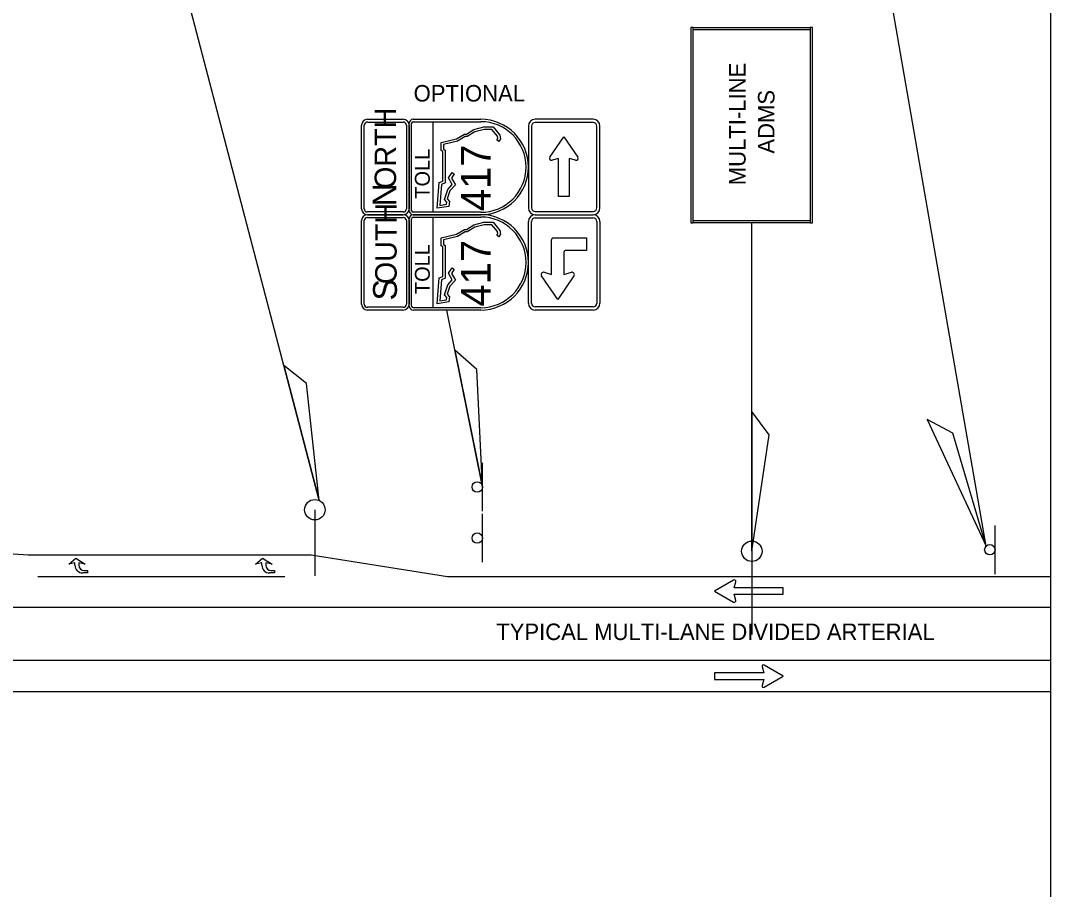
# Model space of a CAD drawing. Extents: x -830008.4 to -829992.7, y 1290284.1 to 1290294.4.
# Drawn here: x -829997.148 to -829992.774, y 1290288.685 to 1290292.375 of the extents above; entities that cross this region are included whole.
import ezdxf

# ---------------------------------------------------------------- set-up
doc = ezdxf.new("R2010")
doc.units = 0
for name, color, linetype in [('1', 7, 'Continuous'), ('DirArrowsPavt', 7, 'Continuous'), ('LaneDirArrow', 7, 'Continuous'), ('OOCEA Logo', 7, 'Continuous'), ('PlotBorder_dp', 7, 'Continuous'), ('SheetBorder_dp', 7, 'Continuous'), ('SheetLines_dp', 7, 'Continuous'), ('SignPanel', 7, 'Continuous')]:
    doc.layers.add(name, color=color, linetype=linetype)

msp = doc.modelspace()

# ---------------------------------------------------------------- linework, layer by layer
at = {"layer": '1'}
for p, q in [((-829993.0471, 1290290.1429), (-829993.4953, 1290292.7228)), ((-829995.8801, 1290290.3367), (-829996.4857, 1290292.6472)), ((-829994.0424, 1290290.1209), (-829994.0424, 1290291.516)), ((-829995.1866, 1290290.3939), (-829995.3374, 1290291.1454)), ((-829997.0749, 1290290.1056), (-829995.9149, 1290290.1056)), ((-829995.9149, 1290290.1056), (-829995.3349, 1290290.0133)), ((-829997.0749, 1290290.0133), (-829996.0258, 1290290.0133)), ((-829995.3349, 1290290.0133), (-829992.7742, 1290290.0133)), ((-829998.578, 1290289.8838), (-829993.659, 1290289.8838)), ((-829993.659, 1290289.8838), (-829992.7742, 1290289.8838)), ((-829998.4483, 1290289.6579), (-829992.7742, 1290289.6579)), ((-829997.6499, 1290289.5251), (-829992.7742, 1290289.5251))]:
    msp.add_line(p, q, dxfattribs=at)
msp.add_arc((-829997.0749, 1290291.317), 1.2114, 238.3217, 270, dxfattribs=at)
at = {"layer": 'DirArrowsPavt'}
for p, q in [((-829996.8778, 1290290.0388), (-829996.8642, 1290290.0388)), ((-829996.0841, 1290290.0388), (-829996.0704, 1290290.0388))]:
    msp.add_line(p, q, dxfattribs=at)
for points in [[(-829996.9175, 1290290.0616), (-829996.9175, 1290290.0721), (-829996.9442, 1290290.0655), (-829996.9142, 1290290.0921), (-829996.8742, 1290290.0655), (-829996.9008, 1290290.0721), (-829996.9008, 1290290.0618)], [(-829996.1237, 1290290.0616), (-829996.1237, 1290290.0721), (-829996.1504, 1290290.0655), (-829996.1204, 1290290.0921), (-829996.0804, 1290290.0655), (-829996.1071, 1290290.0721), (-829996.1071, 1290290.0618)], [(-829996.8642, 1290290.0388), (-829996.8642, 1290290.0288), (-829996.8847, 1290290.0288)], [(-829996.0704, 1290290.0388), (-829996.0704, 1290290.0288), (-829996.0909, 1290290.0288)]]:
    msp.add_lwpolyline(points, dxfattribs=at)
for centre, radius in [((-829996.8847, 1290290.0616), 0.0328), ((-829996.8778, 1290290.0618), 0.023), ((-829996.0909, 1290290.0616), 0.0328), ((-829996.0841, 1290290.0618), 0.023)]:
    msp.add_arc(centre, radius, 180, 270, dxfattribs=at)
at = {"layer": 'LaneDirArrow'}
for p, q in [((-829994.1196, 1290289.9986), (-829994.2004, 1290289.952)), ((-829994.1173, 1290289.9659), (-829994.1105, 1290289.9916)), ((-829993.9087, 1290289.9659), (-829994.1173, 1290289.9659)), ((-829993.9087, 1290289.9381), (-829993.9087, 1290289.9659)), ((-829994.2004, 1290289.952), (-829994.1196, 1290289.9054)), ((-829994.1173, 1290289.9381), (-829993.9087, 1290289.9381)), ((-829994.1105, 1290289.9124), (-829994.1173, 1290289.9381)), ((-829993.9986, 1290289.6301), (-829993.9917, 1290289.6044)), ((-829993.9087, 1290289.5905), (-829993.9895, 1290289.6372)), ((-829993.9917, 1290289.6044), (-829994.2004, 1290289.6044)), ((-829994.2004, 1290289.6044), (-829994.2004, 1290289.5767)), ((-829994.2004, 1290289.5767), (-829993.9917, 1290289.5767)), ((-829993.9917, 1290289.5767), (-829993.9986, 1290289.551)), ((-829993.9895, 1290289.5439), (-829993.9087, 1290289.5905))]:
    msp.add_line(p, q, dxfattribs=at)
for centre, start, end in [((-829994.1165, 1290289.9932), 345, 120), ((-829994.1165, 1290289.9108), 240, 15), ((-829993.9926, 1290289.6318), 60, 195), ((-829993.9926, 1290289.5493), 165, 300)]:
    msp.add_arc(centre, 0.00625, start, end, dxfattribs=at)
at = {"layer": 'OOCEA Logo'}
for p, q in [((-829995.8985, 1290290.2973), (-829995.8985, 1290290.0166)), ((-829994.0424, 1290290.1209), (-829994.0424, 1290289.7674))]:
    msp.add_line(p, q, dxfattribs=at)
for centre in [(-829995.8985, 1290290.2973), (-829995.8985, 1290290.2973), (-829994.0424, 1290290.1209)]:
    msp.add_circle(centre, 0.0434, dxfattribs=at)
at = {"layer": 'PlotBorder_dp'}
for p, q in [((-829995.1866, 1290290.291), (-829995.1866, 1290290.4968)), ((-829995.1866, 1290290.074), (-829995.1866, 1290290.2798)), ((-829993.0094, 1290290.0244), (-829993.0094, 1290290.2302))]:
    msp.add_line(p, q, dxfattribs=at)
for centre in [(-829995.2087, 1290290.3939), (-829995.2087, 1290290.1769), (-829993.0315, 1290290.1273)]:
    msp.add_circle(centre, 0.0221, dxfattribs=at)
at = {"layer": 'SheetBorder_dp'}
for p, q in [((-829995.2966, 1290291.8721), (-829995.2632, 1290291.8929)), ((-829995.2602, 1290291.8823), (-829995.2925, 1290291.8622)), ((-829995.2632, 1290291.8929), (-829995.2548, 1290291.8929)), ((-829995.2518, 1290291.8823), (-829995.2602, 1290291.8823)), ((-829995.2548, 1290291.8929), (-829995.2238, 1290291.9117)), ((-829995.2196, 1290291.9019), (-829995.2518, 1290291.8823)), ((-829995.2238, 1290291.9117), (-829995.1814, 1290291.9233)), ((-829995.18, 1290291.9127), (-829995.2196, 1290291.9019)), ((-829995.1814, 1290291.9233), (-829995.1418, 1290291.9233)), ((-829995.1468, 1290291.9127), (-829995.18, 1290291.9127)), ((-829995.1232, 1290291.8839), (-829995.1468, 1290291.9127)), ((-829995.1418, 1290291.9233), (-829995.1135, 1290291.8887)), ((-829995.1209, 1290291.8745), (-829995.1232, 1290291.8839)), ((-829995.1135, 1290291.8887), (-829995.1095, 1290291.8723)), ((-829994.9003, 1290291.7947), (-829994.8411, 1290291.8809)), ((-829994.8411, 1290291.8809), (-829994.7819, 1290291.7947)), ((-829995.3624, 1290291.8568), (-829995.2966, 1290291.8721)), ((-829995.3624, 1290291.823), (-829995.3624, 1290291.8568)), ((-829995.2925, 1290291.8622), (-829995.3518, 1290291.8484)), ((-829995.3518, 1290291.8484), (-829995.3518, 1290291.8286)), ((-829995.1254, 1290291.8679), (-829995.1209, 1290291.8745)), ((-829995.1168, 1290291.8619), (-829995.1254, 1290291.8679)), ((-829995.1095, 1290291.8723), (-829995.1168, 1290291.8619)), ((-829995.3554, 1290291.8183), (-829995.3624, 1290291.823)), ((-829995.3554, 1290291.6929), (-829995.3554, 1290291.8183)), ((-829995.3518, 1290291.8286), (-829995.3448, 1290291.8239)), ((-829995.3448, 1290291.8239), (-829995.3448, 1290291.6857)), ((-829994.8639, 1290291.7895), (-829994.8907, 1290291.7815)), ((-829994.8639, 1290291.6271), (-829994.8639, 1290291.7895)), ((-829994.7915, 1290291.7815), (-829994.8183, 1290291.7895)), ((-829994.8183, 1290291.7895), (-829994.8183, 1290291.6271)), ((-829995.3313, 1290291.7065), (-829995.3158, 1290291.7293)), ((-829995.3148, 1290291.6784), (-829995.3313, 1290291.7065)), ((-829995.3071, 1290291.7234), (-829995.3188, 1290291.7061)), ((-829995.3188, 1290291.7061), (-829995.3017, 1290291.677)), ((-829995.3158, 1290291.7293), (-829995.3071, 1290291.7234)), ((-829995.3795, 1290291.5774), (-829995.3711, 1290291.6868)), ((-829995.3711, 1290291.6868), (-829995.3554, 1290291.6929)), ((-829995.3611, 1290291.6793), (-829995.368, 1290291.5899)), ((-829995.3448, 1290291.6857), (-829995.3611, 1290291.6793)), ((-829995.334, 1290291.6577), (-829995.3148, 1290291.6784)), ((-829995.3017, 1290291.677), (-829995.3247, 1290291.6522)), ((-829995.3477, 1290291.6155), (-829995.334, 1290291.6577)), ((-829995.3247, 1290291.6522), (-829995.3359, 1290291.6176)), ((-829994.8183, 1290291.6271), (-829994.8639, 1290291.6271)), ((-829995.3295, 1290291.5852), (-829995.3795, 1290291.5774)), ((-829995.368, 1290291.5899), (-829995.339, 1290291.5944)), ((-829995.3379, 1290291.6031), (-829995.3477, 1290291.6155)), ((-829995.339, 1290291.5944), (-829995.3379, 1290291.6031)), ((-829995.3359, 1290291.6176), (-829995.3269, 1290291.6061)), ((-829995.3269, 1290291.6061), (-829995.3295, 1290291.5852)), ((-829995.2966, 1290291.4671), (-829995.2632, 1290291.4879)), ((-829995.2632, 1290291.4879), (-829995.2548, 1290291.4879)), ((-829995.2548, 1290291.4879), (-829995.2238, 1290291.5067)), ((-829995.2196, 1290291.4969), (-829995.2518, 1290291.4773)), ((-829995.2238, 1290291.5067), (-829995.1814, 1290291.5183)), ((-829995.18, 1290291.5077), (-829995.2196, 1290291.4969)), ((-829995.1814, 1290291.5183), (-829995.1418, 1290291.5183)), ((-829995.1468, 1290291.5077), (-829995.18, 1290291.5077)), ((-829995.1232, 1290291.4789), (-829995.1468, 1290291.5077)), ((-829995.1418, 1290291.5183), (-829995.1135, 1290291.4837)), ((-829995.3624, 1290291.4518), (-829995.2966, 1290291.4671)), ((-829995.3624, 1290291.418), (-829995.3624, 1290291.4518)), ((-829995.2925, 1290291.4572), (-829995.3518, 1290291.4434)), ((-829995.3518, 1290291.4434), (-829995.3518, 1290291.4236)), ((-829995.2602, 1290291.4773), (-829995.2925, 1290291.4572)), ((-829995.2518, 1290291.4773), (-829995.2602, 1290291.4773)), ((-829995.1254, 1290291.4629), (-829995.1209, 1290291.4695)), ((-829995.1168, 1290291.4569), (-829995.1254, 1290291.4629)), ((-829995.1209, 1290291.4695), (-829995.1232, 1290291.4789)), ((-829995.1095, 1290291.4673), (-829995.1168, 1290291.4569)), ((-829995.1135, 1290291.4837), (-829995.1095, 1290291.4673)), ((-829994.8935, 1290291.2964), (-829994.8935, 1290291.4436)), ((-829994.8854, 1290291.4517), (-829994.7446, 1290291.4517)), ((-829994.7446, 1290291.4517), (-829994.7446, 1290291.3986)), ((-829995.3554, 1290291.4133), (-829995.3624, 1290291.418)), ((-829995.3554, 1290291.2879), (-829995.3554, 1290291.4133)), ((-829995.3518, 1290291.4236), (-829995.3448, 1290291.4189)), ((-829995.3448, 1290291.4189), (-829995.3448, 1290291.2807)), ((-829994.8403, 1290291.3905), (-829994.8403, 1290291.2964)), ((-829994.7446, 1290291.3986), (-829994.8322, 1290291.3986)), ((-829995.3313, 1290291.3015), (-829995.3158, 1290291.3243)), ((-829995.3071, 1290291.3184), (-829995.3188, 1290291.3011)), ((-829995.3158, 1290291.3243), (-829995.3071, 1290291.3184)), ((-829995.3795, 1290291.1724), (-829995.3711, 1290291.2818)), ((-829995.3711, 1290291.2818), (-829995.3554, 1290291.2879)), ((-829995.3611, 1290291.2743), (-829995.368, 1290291.1849)), ((-829995.3448, 1290291.2807), (-829995.3611, 1290291.2743)), ((-829995.334, 1290291.2527), (-829995.3148, 1290291.2734)), ((-829995.3148, 1290291.2734), (-829995.3313, 1290291.3015)), ((-829995.3017, 1290291.272), (-829995.3247, 1290291.2472)), ((-829995.3188, 1290291.3011), (-829995.3017, 1290291.272)), ((-829994.8669, 1290291.1897), (-829994.936, 1290291.2903)), ((-829994.9247, 1290291.3057), (-829994.8935, 1290291.2964)), ((-829994.7978, 1290291.2903), (-829994.8669, 1290291.1897)), ((-829994.8403, 1290291.2964), (-829994.809, 1290291.3057)), ((-829995.3477, 1290291.2105), (-829995.334, 1290291.2527)), ((-829995.3247, 1290291.2472), (-829995.3359, 1290291.2126)), ((-829995.368, 1290291.1849), (-829995.339, 1290291.1894)), ((-829995.3379, 1290291.1981), (-829995.3477, 1290291.2105)), ((-829995.339, 1290291.1894), (-829995.3379, 1290291.1981)), ((-829995.3359, 1290291.2126), (-829995.3269, 1290291.2011)), ((-829995.3269, 1290291.2011), (-829995.3295, 1290291.1802)), ((-829995.3295, 1290291.1802), (-829995.3795, 1290291.1724))]:
    msp.add_line(p, q, dxfattribs=at)
for points in [[(-829994.3009, 1290292.346), (-829994.3009, 1290291.516), (-829994.2909, 1290291.516), (-829994.2909, 1290292.346)], [(-829993.794, 1290292.346), (-829993.794, 1290292.336), (-829994.2909, 1290292.336), (-829994.2909, 1290292.346)], [(-829993.784, 1290291.516), (-829993.784, 1290292.346), (-829993.794, 1290292.346), (-829993.794, 1290291.516)], [(-829994.2909, 1290291.516), (-829994.2909, 1290291.526), (-829993.794, 1290291.526), (-829993.794, 1290291.516)]]:
    msp.add_lwpolyline(points, close=True, dxfattribs=at)
for points in [[(-829995.7002, 1290291.5757), (-829995.7002, 1290291.9301)], [(-829995.6886, 1290291.5757), (-829995.6886, 1290291.9301)], [(-829995.6749, 1290291.9554), (-829995.523, 1290291.9554)], [(-829995.6749, 1290291.9438), (-829995.523, 1290291.9438)], [(-829995.5093, 1290291.9301), (-829995.5093, 1290291.5757)], [(-829995.4977, 1290291.5673), (-829995.4977, 1290291.9385)], [(-829995.4977, 1290291.9301), (-829995.4977, 1290291.5757)], [(-829995.4875, 1290291.5673), (-829995.4875, 1290291.9385)], [(-829995.4808, 1290291.9554), (-829995.1939, 1290291.9554)], [(-829995.4808, 1290291.9453), (-829995.1939, 1290291.9453)], [(-829995.3964, 1290291.5605), (-829995.3964, 1290291.9453)], [(-829994.9914, 1290291.9265), (-829994.9914, 1290291.5793)], [(-829994.9782, 1290291.9265), (-829994.9782, 1290291.5793)], [(-829994.7166, 1290291.9554), (-829994.9625, 1290291.9554)], [(-829994.7166, 1290291.9421), (-829994.9625, 1290291.9421)], [(-829994.7009, 1290291.5793), (-829994.7009, 1290291.9265)], [(-829994.6877, 1290291.5793), (-829994.6877, 1290291.9265)], [(-829995.523, 1290291.562), (-829995.6749, 1290291.562)], [(-829995.6749, 1290291.5504), (-829995.523, 1290291.5504)], [(-829995.523, 1290291.5504), (-829995.6749, 1290291.5504)], [(-829995.6749, 1290291.5388), (-829995.523, 1290291.5388)], [(-829995.4977, 1290291.1623), (-829995.4977, 1290291.5335)], [(-829995.4875, 1290291.1623), (-829995.4875, 1290291.5335)], [(-829995.1939, 1290291.5605), (-829995.4808, 1290291.5605)], [(-829995.1939, 1290291.5504), (-829995.4808, 1290291.5504)], [(-829995.4808, 1290291.5504), (-829995.1939, 1290291.5504)], [(-829995.4808, 1290291.5403), (-829995.1939, 1290291.5403)], [(-829995.3964, 1290291.1555), (-829995.3964, 1290291.5403)], [(-829994.9625, 1290291.5637), (-829994.7166, 1290291.5637)], [(-829994.9625, 1290291.5504), (-829994.7166, 1290291.5504)], [(-829994.9625, 1290291.5504), (-829994.7166, 1290291.5504)], [(-829994.9625, 1290291.5371), (-829994.7166, 1290291.5371)], [(-829995.7002, 1290291.1707), (-829995.7002, 1290291.5251)], [(-829995.6886, 1290291.1707), (-829995.6886, 1290291.5251)], [(-829995.5093, 1290291.5251), (-829995.5093, 1290291.1707)], [(-829995.4977, 1290291.5251), (-829995.4977, 1290291.1707)], [(-829994.9914, 1290291.1743), (-829994.9914, 1290291.5215)], [(-829994.9782, 1290291.1743), (-829994.9782, 1290291.5215)], [(-829994.7009, 1290291.5215), (-829994.7009, 1290291.1743)], [(-829994.6877, 1290291.5215), (-829994.6877, 1290291.1743)], [(-829995.523, 1290291.157), (-829995.6749, 1290291.157)], [(-829995.523, 1290291.1454), (-829995.6749, 1290291.1454)], [(-829995.1939, 1290291.1555), (-829995.4808, 1290291.1555)], [(-829995.1939, 1290291.1454), (-829995.4808, 1290291.1454)], [(-829994.7166, 1290291.1587), (-829994.9625, 1290291.1587)], [(-829994.7166, 1290291.1454), (-829994.9625, 1290291.1454)]]:
    msp.add_lwpolyline(points, dxfattribs=at)
for centre, radius, start, end in [((-829995.6749, 1290291.9301), 0.0253, 90, 180), ((-829995.6749, 1290291.9301), 0.0137, 90, 180), ((-829995.523, 1290291.9301), 0.0253, 0, 90), ((-829995.523, 1290291.9301), 0.0137, 0, 90), ((-829995.4808, 1290291.9385), 0.0169, 90, 180), ((-829995.4808, 1290291.9385), 0.00675, 90, 180), ((-829995.1939, 1290291.7529), 0.2025, 270, 90), ((-829995.1939, 1290291.7529), 0.1924, 270, 90), ((-829994.9625, 1290291.9265), 0.0289, 90, 180), ((-829994.9625, 1290291.9265), 0.0157, 90.0544, 180), ((-829994.7166, 1290291.9265), 0.0289, 0, 90), ((-829994.7166, 1290291.9265), 0.0157, 0, 90), ((-829994.8932, 1290291.7898), 0.00868, 145.5119, 286.6443), ((-829994.789, 1290291.7898), 0.00868, 253.3557, 34.4881), ((-829995.6749, 1290291.5757), 0.0253, 180, 270), ((-829995.6749, 1290291.5757), 0.0137, 180, 270), ((-829995.523, 1290291.5757), 0.0253, 270, 0), ((-829995.523, 1290291.5757), 0.0137, 270, 0), ((-829994.9625, 1290291.5793), 0.0289, 180, 270), ((-829994.9625, 1290291.5793), 0.0157, 180, 269.9456), ((-829994.7166, 1290291.5793), 0.0157, 270, 360), ((-829994.7166, 1290291.5793), 0.0289, 270, 360), ((-829995.6749, 1290291.5251), 0.0253, 90, 180), ((-829995.6749, 1290291.5251), 0.0137, 90, 180), ((-829995.523, 1290291.5251), 0.0253, 0, 90), ((-829995.523, 1290291.5251), 0.0137, 0, 90), ((-829995.4808, 1290291.5673), 0.0169, 180, 270), ((-829995.4808, 1290291.5335), 0.0169, 90, 180), ((-829995.4808, 1290291.5673), 0.00675, 180, 270), ((-829995.4808, 1290291.5335), 0.00675, 90, 180), ((-829995.1939, 1290291.3479), 0.2025, 270, 90), ((-829995.1939, 1290291.3479), 0.1924, 270, 90), ((-829994.9625, 1290291.5215), 0.0289, 90, 180), ((-829994.9625, 1290291.5215), 0.0157, 90.0544, 180), ((-829994.7166, 1290291.5215), 0.0289, 0, 90), ((-829994.7166, 1290291.5215), 0.0157, 0, 90), ((-829994.8854, 1290291.4436), 0.0081, 90, 180), ((-829994.8322, 1290291.3905), 0.0081, 90, 180), ((-829994.9276, 1290291.296), 0.0101, 73.3557, 214.4881), ((-829994.8061, 1290291.296), 0.0101, 325.5119, 106.6443), ((-829995.6749, 1290291.1707), 0.0253, 180, 270), ((-829995.6749, 1290291.1707), 0.0137, 180, 270), ((-829995.523, 1290291.1707), 0.0253, 270, 360), ((-829995.523, 1290291.1707), 0.0137, 270, 360), ((-829995.4808, 1290291.1623), 0.0169, 180, 270), ((-829995.4808, 1290291.1623), 0.00675, 180, 270), ((-829994.9625, 1290291.1743), 0.0289, 180, 270), ((-829994.9625, 1290291.1743), 0.0157, 180, 269.9456), ((-829994.7166, 1290291.1743), 0.0289, 270, 360), ((-829994.7166, 1290291.1743), 0.0157, 270, 360)]:
    msp.add_arc(centre, radius, start, end, dxfattribs=at)
at = {"layer": 'SheetLines_dp'}
msp.add_lwpolyline([(-830007.4742, 1290294.228), (-829992.7742, 1290294.228), (-829992.7742, 1290285.328), (-830007.4742, 1290285.328)], close=True, dxfattribs=at)
at = {"layer": 'SignPanel'}
for p, q in [((-829995.2111, 1290290.8933), (-829995.3033, 1290290.9757)), ((-829995.3033, 1290290.9757), (-829995.1866, 1290290.3939)), ((-829995.9337, 1290290.8338), (-829996.0305, 1290290.9106)), ((-829996.0305, 1290290.9106), (-829995.8801, 1290290.3367)), ((-829995.1866, 1290290.3939), (-829995.2111, 1290290.8933)), ((-829995.8801, 1290290.3367), (-829995.9337, 1290290.8338)), ((-829993.9683, 1290290.6153), (-829994.0424, 1290290.7142)), ((-829994.0424, 1290290.7142), (-829994.0424, 1290290.1209)), ((-829993.189, 1290290.6224), (-829993.298, 1290290.6806)), ((-829993.298, 1290290.6806), (-829993.0471, 1290290.1429)), ((-829994.0424, 1290290.1209), (-829993.9683, 1290290.6153)), ((-829993.0471, 1290290.1429), (-829993.189, 1290290.6224))]:
    msp.add_line(p, q, dxfattribs=at)

# ---------------------------------------------------------------- texts
at = {"layer": '1'}
for s, rotation, p in [('MULTI-LINE', 90.0044, (-829994.0687, 1290291.6755)), ('OPTIONAL ', 0.0044, (-829995.479, 1290292.0311)), ('ADMS', 90.0044, (-829993.9462, 1290291.8097)), ('TYPICAL MULTI-LANE DIVIDED ARTERIAL', 0.0044, (-829995.128, 1290289.7439))]:
    msp.add_text(s, height=0.07, rotation=rotation, dxfattribs=at).set_placement(p)
at = {"layer": 'SheetBorder_dp'}
for s, height, p in [('ORTH', 0.09113, (-829995.5535, 1290291.6598)), ('417', 0.12656, (-829995.1517, 1290291.5655)), ('TOLL', 0.06328, (-829995.4103, 1290291.6185)), ('N', 0.1013, (-829995.5523, 1290291.5859)), ('OUTH', 0.09113, (-829995.5511, 1290291.2555)), ('TOLL', 0.06328, (-829995.4103, 1290291.2135)), ('417', 0.12656, (-829995.1517, 1290291.1605)), ('S', 0.1013, (-829995.55, 1290291.1862))]:
    msp.add_text(s, height=height, rotation=90, dxfattribs=at).set_placement(p)

doc.saveas('drawing.dxf')
